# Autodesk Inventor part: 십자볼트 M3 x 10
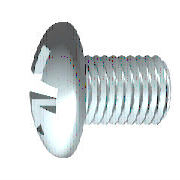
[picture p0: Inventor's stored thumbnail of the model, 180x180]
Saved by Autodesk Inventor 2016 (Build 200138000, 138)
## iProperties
IsCustomPart: 0
Created: 2012-02
Part Number: 십자볼트 M3 x 10
Material: 스테인리스강
Description: 십자 오목 머리 나사
Document SubType Name: Modeling
Standard: KS B 1023
Designer: mduedu
Standards Organization: KS
Language: ko-KR
Size Designation: A  M 3 x 10 - H
Categories: <MemberInstance><Categories><Category DisplayName="조임쇠" InternalName="e4da775c-781d-43d5-af7c-5136215cf5a6" Mnemonic="FSTN"><Category DisplayName="볼트" InternalN
Density: 1 g/cm^3
Appearance: 반광택
Author: mduedu
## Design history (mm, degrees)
body "Solid1"
workplane "Work Plane3"
sketch "스케치2"
  geometry: L1 (-3.72, 0)-(3.72, 0) reference; L2 (0, -3.72)-(0, 3.72) reference; L3 (0, 1.5)-(0, 0); L4 (0, 0)-(1.5, 0); L5 (0, 0)-(1.879, 1.879); L6 (0.253, 1.479)-(0.261, 0.456); L7 (1.479, 0.253)-(0.456, 0.261); L8 (0.253, -1.479)-(0.261, -0.456); L9 (1.479, -0.253)-(0.456, -0.261); L10 (-0.253, 1.479)-(-0.261, 0.456); L11 (-1.479, 0.253)-(-0.456, 0.261); L12 (-1.479, -0.253)-(-0.456, -0.261); L13 (-0.253, -1.479)-(-0.261, -0.456); A1 r 0.45 centre (0, 0) between (0.45, 0) and (0, 0.45); A2 r 1.5 centre (0, 0) between (1.5, 0) and (1.479, 0.253); A3 r 1.5 centre (0, 0) between (0.253, 1.479) and (0, 1.5); A4 r 1.5 centre (0, 0) between (1.479, 0.253) and (0.253, 1.479); A5 r 1.5 centre (0, 0) between (0, -1.5) and (0.253, -1.479); A6 r 1.5 centre (0, 0) between (0.253, -1.479) and (1.479, -0.253); A7 r 1.5 centre (0, 0) between (1.479, -0.253) and (1.5, 0); A8 r 1.5 centre (0, 0) between (-1.479, 0.253) and (-1.5, 0); A9 r 1.5 centre (0, 0) between (-0.253, 1.479) and (-1.479, 0.253); A10 r 1.5 centre (0, 0) between (0, 1.5) and (-0.253, 1.479); A11 r 1.5 centre (0, 0) between (-1.5, 0) and (-1.479, -0.253); A12 r 1.5 centre (0, 0) between (-1.479, -0.253) and (-0.253, -1.479); A13 r 1.5 centre (0, 0) between (-0.253, -1.479) and (0, -1.5); A14 r 0.525 centre (0, 0) between (0.525, 0) and (0, 0.525); A15 r 0.197 centre (0.457, 0.457) between (0.261, 0.456) and (0.456, 0.261); A16 r 0.197 centre (0.457, -0.457) between (0.456, -0.261) and (0.261, -0.456); A17 r 0.197 centre (-0.457, 0.457) between (-0.456, 0.261) and (-0.261, 0.456); A18 r 0.197 centre (-0.457, -0.457) between (-0.261, -0.456) and (-0.456, -0.261); 1 further point
  constraints: 38 point on circle, 22 end point, 19 symmetric about line, 18 centre point, 4 coincident, 3 collinear, 3 point on line, 3 tangent, 1 perpendicular, 21 other
  dimensions: "d4" = 45 deg angle of L5 L4; "d5" = 0.9 diameter of A1 (= 0.3 x SDM); "d6" = 3 diameter of A4 (= SDM); "d7" = 0.2525 distance from line of L6.start L3 (= 0.5 x SBR); "d14" = 1.05 diameter of A14 (= 0.35 x SDM)
extrude "슬롯" join sketch "스케치2" taper "d15" = 5 deg; stored distance "d54" = 10
revolve "절단부" stored, may be unused: angle "d56" = 90 deg
revolve "본체" stored, may be unused: angle "d18" = 90 deg
workplane "Work Plane1"
sketch "스케치1"
  geometry: L1 (10, 0)-(10, 1.5); L2 (10, 1.5)-(1, 1.5); L3 (3.962, 5.08)-(3.962, 5.08); L4 (-2.4, 0)-(-2.4, 2.59); L5 (-2.2, 1.4)-(-1.036, 0.82); L6 (-1.036, 0.82)-(-0.6, 0); L7 (-0.6, 0)-(10, 0); L8 (-5.105, 0)-(12.517, 0) reference; L9 (0, -1.016)-(0, 6.096) reference; L10 (-2.2, 1.4)-(-2.4, 1.5); L11 (-1.636, 2.657)-(-2.4, 2.59); L12 (-1.636, 2.657)-(0, 2.8); L13 (0, 2.8)-(0, 1.347); L14 (0, 1.347)-(0.693, 1.347); L15 (0.693, 1.347)-(1, 1.5); L16 (1, 1.5)-(0, 1.5); A1 r 5 centre (2.6, 0) between (-1.636, 2.657) and (-2.4, 0)
  constraints: 28 end point, 5 point on line, 4 collinear, 4 point on circle, 3 parallel, 2 perpendicular, 1 centre point, 1 horizontal, 1 tangent
  dimensions: "d1" = 3 diameter of L2 L7 (= GD); "d2" = 1.8 distance from line of L6.end L4 (= STI); "d11" = 3 diameter of L10.end L7 (= SDM); "d12" = 62 deg angle of L6 L7; "d13" = 26.5 deg angle of L5 L7; "d17" = 5.6 diameter of L12.end L7 (= KOD); "d19" = 5 deg angle of L12 L7 (= KEWI); "d20" = 2.4 distance between parallel lines of L4 L13 (= KOH); "d21" = 5 radius of A1 (= KR); "d23" = 2.6935 diameter of L14 L7 (= BDM); "d24" = 9 distance of L1.end L2.end (= GEL); "d25" = 0.30673 horizontal distance of L14.end L2.end (= GAL); "d28" = 10 distance between parallel lines of L1 L13 (= NLG)
fillet "모깎기1" dims "d29" = 1.2 (= RR)
fillet "모깎기2" dims "d16" = 0.101 (= 0.2 x SBR)
feature "스레드" dims "d8" = 9 (= GEL), "d9" = 0
chamfer "모따기1" distance "d26" = 0.30673 (= -0.5 x SPD + 0.5 x GD); stored, may be unused: second distance "d27" = 0.30683 (computed from GUL), angle "d78" = 45 deg
other parameters: "GD" = 3 (= NND) [user parameter; used in 2 equation terms], "NLG" = 10 [user parameter; used in 1 equation term], "GEL" = 9 [user parameter; used in 2 equation terms], "KOD" = 5.6 [user parameter; used in 1 equation term], "KOH" = 2.4 [user parameter; used in 2 equation terms], "SDM" = 3 [user parameter; used in 4 equation terms], "STI" = 1.8 [user parameter; used in 1 equation term], "SBR" = 0.505 [user parameter; used in 2 equation terms], "GAL" = 0.30673 (= 0.61345 x PTC) [user parameter; used in 1 equation term], "SPD" = 2.38655 (= NND - 1.2269 x PTC) [user parameter; used in 1 equation term], "KEWI" = 5 deg [user parameter; used in 1 equation term], "d3" = -2.4 (= -KOH), "d10" = 0, "KR" = 5 [user parameter; used in 1 equation term], "BDM" = 2.6935 [user parameter; used in 1 equation term], "GUL" = 0.30673 (= 0.61345 x PTC) [user parameter; used in 1 equation term], "RR" = 1.2 [user parameter; used in 1 equation term], "d79" = 0, "d80" = 0, "PTC" = 0.5 [user parameter; used in 5 equation terms], "THREADDIA" = 3 [user parameter; used in 1 equation term], "TOA" = 30 deg [user parameter], "NND" = 3 [user parameter; used in 2 equation terms], "GD1" = 2.38655 (= THREADDIA - 1.2269 x PTC) [user parameter]
